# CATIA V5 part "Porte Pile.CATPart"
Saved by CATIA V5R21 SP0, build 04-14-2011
Part number: Porte piles
Bounding box of the stored display mesh (mm): x -7 to 20, y 0 to 105, z 0 to 69
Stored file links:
  C:\Users\2027.DESARCY-LEMIE30\Desktop\V15(20.03.2023)\Porte Pile.CATPart
  D:\carte arduino.CATPart
  C:\Users\2027.DESARCY-LEMIE30\Desktop\attachments\Fixation carte arduino v3.CATPart
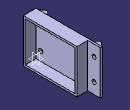
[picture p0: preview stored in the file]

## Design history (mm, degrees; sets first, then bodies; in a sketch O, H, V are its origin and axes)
Body1 (main body)
  Sketch1 on yz-plane, origin (0, 0, 0), H (0, 1, 0), V (0, 0, 1)
    line L1 (0, 0) -> (105, 0)
    line L2 (105, 0) -> (105, 69)
    line L3 (105, 69) -> (0, 69)
    line L4 (0, 69) -> (0, 0)
    length L3 = 105
    length L2 = 69
    horizontal: L1 H, L3 H
    vertical: L2 V, L4 V
  Pad1: profile Sketch1, direction (1, 0, 0), length 3
  Sketch2 on end face of Pad1, origin (3, 0, 0), H (0, 1, 0), V (0, 0, 1)
    line L1 (0, 69) -> (85, 69)
    line L2 (85, 69) -> (85, 0)
    line L3 (85, 0) -> (0, 0)
    line L4 (0, 0) -> (0, 69)
    point P4 (0, 0)
    reference projected line E1 (110, 69) -> (0, 69) from edge [face of Pad1 from Sketch1.L3 | end face of Pad1]
    reference projected line E2 (0, 0) -> (105, 0) from edge [face of Pad1 from Sketch1.L1 | end face of Pad1]
    line L5 (3, 66) -> (82, 66)
    line L6 (82, 66) -> (82, 3)
    line L7 (82, 3) -> (3, 3)
    line L8 (3, 3) -> (3, 66)
    distance L5 L1 = 3
    distance L7 L3 = 3
    distance L6 L2 = 3
    distance L8 L4 = 3
    distance L8 L6 = 79
    horizontal: L1 H, L3 H, L5 H, L7 H
    vertical: L2 V, L4 V, L6 V, L8 V
    coincidence: L1 E1, L3 E2, O P4
  Pad2: profile Sketch2, direction (1, 0, 0), length 17
  Sketch3 on face of Pad2, origin (0, 0, 0), H (1, 0, 0), V (0, -1, 0)
    construction line L1 (-26.9072, -52.5) -> (75.9513, -52.5)
    reference projected line E1 (0, -105) -> (3, -105) from edge [face of Pad1 from Sketch1.L2 | face of Pad1 from Sketch1.L1]
    axis line L2 (-22.3256, -9.9) -> (35.4035, -9.9)
    point P5 (0, -6.9)
    line L3 (0, -6.9) -> (-2.1, -6.9)
    point P6 (-2.1, -6.9)
    line L4 (-2.1, -6.9) -> (-2.1, -3.1)
    point P7 (-2.1, -3.1)
    line L5 (-2.1, -3.1) -> (-7, -8)
    point P8 (-7, -8)
    line L6 (-7, -8) -> (-7, -9.9)
    point P9 (-7, -9.9)
    point P10 (0, -9.9)
    line L7 (0, -9.9) -> (0, -6.9)
    reference projected line E2 (0, 0) -> (0, -105) from edge [start face of Pad1 | face of Pad1 from Sketch1.L1]
    point P11 (0, -12.9)
    point P12 (-2.1, -12.9)
    point P13 (-2.1, -16.7)
    point P14 (-7, -11.8)
    point P15 (-7, -9.9)
    point P16 (0, -9.9)
    line L8 (0, -12.9) -> (-2.1, -12.9)
    line L9 (-2.1, -12.9) -> (-2.1, -16.7)
    line L10 (-2.1, -16.7) -> (-7, -11.8)
    line L11 (-7, -11.8) -> (-7, -9.9)
    line L12 (0, -9.9) -> (0, -12.9)
    point P17 (0, -98.1)
    point P18 (-2.1, -98.1)
    point P19 (-2.1, -101.9)
    point P20 (-7, -97)
    point P21 (-7, -95.1)
    point P22 (0, -95.1)
    point P23 (0, -92.1)
    point P24 (-2.1, -92.1)
    point P25 (-2.1, -88.3)
    point P26 (-7, -93.2)
    point P27 (-7, -95.1)
    point P28 (0, -95.1)
    line L13 (0, -98.1) -> (-2.1, -98.1)
    line L14 (-2.1, -98.1) -> (-2.1, -101.9)
    line L15 (-2.1, -101.9) -> (-7, -97)
    line L16 (-7, -97) -> (-7, -95.1)
    line L17 (0, -95.1) -> (0, -98.1)
    line L18 (0, -92.1) -> (-2.1, -92.1)
    line L19 (-2.1, -92.1) -> (-2.1, -88.3)
    line L20 (-2.1, -88.3) -> (-7, -93.2)
    line L21 (-7, -93.2) -> (-7, -95.1)
    line L22 (0, -95.1) -> (0, -92.1)
    reference projected line E3 (0, 0) -> (3, 0) from edge [face of Pad2 | face of Pad2]
    distance E1 L1 = 52.5
    length L7 = 3
    length L4 = 3.8
    angle L5 L4 = 45
    length L6 = 1.9
    distance L6 L7 = 7
    distance L3 E3 = 6.9
    horizontal: L1 H, L2 H, L3 H
    vertical: L4 V, L6 V, L7 V
    coincidence: P9 L2, P10 L2, L7 E2, P9 P15, P10 P16, P21 P27, P22 P28
    symmetry: P5 P11 L2, P6 P12 L2, P7 P13 L2, P8 P14 L2, P9 P15 L2, P10 P16 L2, L3 L8 L2, L4 L9 L2, L5 L10 L2, L6 L11 L2, L7 L12 L2, P5 P17 L1, P6 P18 L1, P7 P19 L1, P8 P20 L1, P9 P21 L1, P10 P22 L1, P11 P23 L1, P12 P24 L1, P13 P25 L1, P14 P26 L1, P15 P27 L1, P16 P28 L1, L3 L13 L1, L4 L14 L1, L5 L15 L1, L6 L16 L1, L7 L17 L1, L8 L18 L1, L9 L19 L1, L10 L20 L1, L11 L21 L1, L12 L22 L1
  Pad3: profile Sketch3, direction (0, 0, 1), length 67
  Sketch4 on end face of Pad1, origin (3, 16.9157, 27.9903), H (0, 1, 0), V (0, 0, 1)
    point P1 (78.1843, 23.7597)
    construction line L1 (-16.9157, 6.5097) -> (88.0843, 6.5097)
    point P2 (-16.9157, 6.5097)
    point P3 (88.0843, 6.5097)
    reference projected line E1 (88.0843, -27.9903) -> (88.0843, 40.0097) from edge [face of Pad1 from Sketch1.L2 | end face of Pad1]
    reference projected line E2 (-16.9157, 41.0097) -> (-16.9157, -27.9903) from edge [face of Pad2 | end face of Pad2]
    construction line L2 (35.5843, 6.5097) -> (35.5843, 41.0097)
    point P4 (35.5843, 6.5097)
    point P5 (35.5843, 41.0097)
    reference projected line E3 (68.0843, 41.0097) -> (-16.9157, 41.0097) from edge [face of Pad3 | end face of Pad2]
    reference projected line E4 (93.0843, 41.0097) -> (-16.9157, 41.0097) from edge [face of Pad3 | end face of Pad1]
    reference projected line E5 (-16.9157, -27.9903) -> (88.0843, -27.9903) from edge [face of Pad3 | end face of Pad1]
    reference projected line E6 (93.0843, 41.0097) -> (-16.9157, 41.0097) from edge [face of Pad3 | end face of Pad1]
    construction line L3 (35.5843, 23.7597) -> (88.0843, 23.7597)
    point P6 (35.5843, 23.7597)
    point P7 (88.0843, 23.7597)
    reference projected line E7 (88.0843, -27.9903) -> (88.0843, 40.0097) from edge [face of Pad1 from Sketch1.L2 | end face of Pad1]
    axis line L4 (78.1843, 41.0097) -> (78.1843, -27.9903)
    point P8 (78.1843, 41.0097)
    point P9 (78.1843, -27.9903)
    reference projected line E8 (68.0843, 41.0097) -> (-16.9157, 41.0097) from edge [face of Pad3 | end face of Pad2]
    reference projected line E9 (-16.9157, -27.9903) -> (68.0843, -27.9903) from edge [face of Pad3 | end face of Pad2]
    reference projected line E10 (88.0843, -27.9903) -> (88.0843, 40.0097) from edge [face of Pad1 from Sketch1.L2 | end face of Pad1]
    distance E4 E5 = 69 (reference)
    distance L1 E6 = 34.5
    distance L4 E10 = 9.9
    horizontal: L1 H, L3 H
    coincidence: P3 E1, P2 E2, P5 E3, P7 E7, E8 P8, P9 E9, P1 L4, P1 L3
    vertical: L2 V, L4 V
    midpoint: P4 L1, P6 L2
  Hole1: placed by Sketch4, at (3, 95.1, 51.75) direction (-1, 0, 0), diameter 3.8, depth 12, counterbore diameter 6.8, counterbore depth 4
  RectPattern1: of Hole1, direction 1 instances 2, spacing 84.7, along end face of Pad1 reversed, direction 2 instances 2, spacing -34.5, along end face of Pad1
